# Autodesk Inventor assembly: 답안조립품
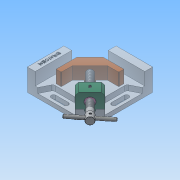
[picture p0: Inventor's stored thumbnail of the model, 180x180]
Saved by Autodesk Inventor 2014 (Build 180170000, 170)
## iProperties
Created: 2019-04
Part Number: 답안조립품
Document SubType Name: Assembly
Designer: net
Author: net
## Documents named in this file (11)
- C:\Users\net\Desktop\490407V1030\답안조립품.iam
- C:\Users\net\Desktop\490407V1030\본체.ipt
- C:\Users\net\Desktop\490407V1030\리드스크류.ipt
- C:\Users\net\Desktop\490407V1030\멈춤나사 M4x5.ipt
- C:\Users\net\Desktop\490407V1030\멈춤나사 M4x10.ipt
- C:\Users\net\Desktop\490407V1030\볼트 M4x16.ipt
- C:\Users\net\Desktop\490407V1030\부시.ipt
- C:\Users\net\Desktop\490407V1030\서포트.ipt
- C:\Users\net\Desktop\490407V1030\조.ipt
- C:\Users\net\Desktop\490407V1030\평행 핀 2.5x24.ipt
- C:\Users\net\Desktop\490407V1030\핸들.ipt
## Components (1 placed, 1 different names)
1. 핸들:1
